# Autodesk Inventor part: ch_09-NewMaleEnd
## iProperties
Shininess: 0.0
Length Units: 11269
Angle Units: 11279
Time Units: 11290
Mass Units: 11283
Length Display Precision: 3
Angle Display Precision: 1
Compacted: True
Created: 1999-06
Part Number: ch_09-NewMaleEnd
Document SubType Name: Modeling
Designer: Administrator
Density: 1 g/cm^3
Density: 0.0
Volumn: 0.0
Area: 0.0
PropertySet Name: Model Information
Control State: 0
Master: False
Checked Out: False
Author: Administrator
